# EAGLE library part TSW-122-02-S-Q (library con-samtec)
THROUGH-HOLE .025" SQ POST HEADER Source: Samtec TSW.pdf
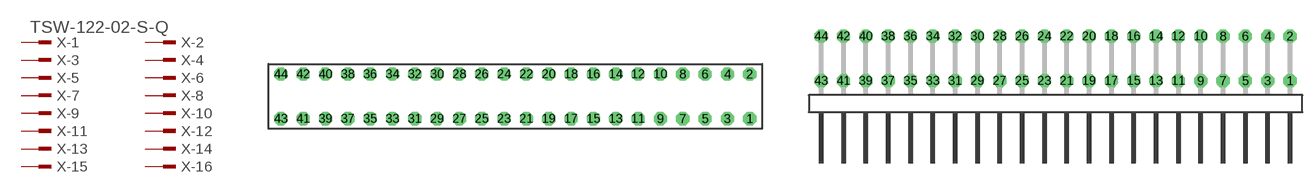
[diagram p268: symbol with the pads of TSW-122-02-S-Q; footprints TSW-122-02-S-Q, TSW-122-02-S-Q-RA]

Designator prefix X; gates -1=MPINV -2=MPIN -3=MPIN -4=MPIN -5=MPIN -6=MPIN -7=MPIN -8=MPIN -9=MPIN -10=MPIN -11=MPIN -12=MPIN -13=MPIN -14=MPIN -15=MPIN -16=MPIN -17=MPIN -18=MPIN -19=MPIN -20=MPIN -21=MPIN -22=MPIN -23=MPIN -24=MPIN -25=MPIN -26=MPIN -27=MPIN -28=MPIN -29=MPIN -30=MPIN -31=MPIN -32=MPIN -33=MPIN -34=MPIN -35=MPIN -36=MPIN -37=MPIN -38=MPIN -39=MPIN -40=MPIN -41=MPIN -42=MPIN -43=MPIN -44=MPIN

## TSW-122-02-S-Q (OC_FARNELL: unknown; OC_NEWARK: unknown)  [TSW-122-02-S-Q]
1  -1:1  pas
2  -2:1  pas
3  -3:1  pas
4  -4:1  pas
5  -5:1  pas
6  -6:1  pas
7  -7:1  pas
8  -8:1  pas
9  -9:1  pas
10  -10:1  pas
11  -11:1  pas
12  -12:1  pas
13  -13:1  pas
14  -14:1  pas
15  -15:1  pas
16  -16:1  pas
17  -17:1  pas
18  -18:1  pas
19  -19:1  pas
20  -20:1  pas
21  -21:1  pas
22  -22:1  pas
23  -23:1  pas
24  -24:1  pas
25  -25:1  pas
26  -26:1  pas
27  -27:1  pas
28  -28:1  pas
29  -29:1  pas
30  -30:1  pas
31  -31:1  pas
32  -32:1  pas
33  -33:1  pas
34  -34:1  pas
35  -35:1  pas
36  -36:1  pas
37  -37:1  pas
38  -38:1  pas
39  -39:1  pas
40  -40:1  pas
41  -41:1  pas
42  -42:1  pas
43  -43:1  pas
44  -44:1  pas

## TSW-122-02-S-Q-RA (OC_FARNELL: unknown; OC_NEWARK: unknown)  [TSW-122-02-S-Q-RA]
Pads as for TSW-122-02-S-Q

## Footprint TSW-122-02-S-Q (pad centres in mm)
THROUGH-HOLE .025" SQ POST HEADER Source: Samtec TSW.pdf
drill 1 pad 1.5 octagon: 1 26.67,-2.54; 2 26.67,2.54; 3 24.13,-2.54; 4 24.13,2.54; 5 21.59,-2.54; 6 21.59,2.54; 7 19.05,-2.54; 8 19.05,2.54; 9 16.51,-2.54; 10 16.51,2.54; 11 13.97,-2.54; 12 13.97,2.54; 13 11.43,-2.54; 14 11.43,2.54; 15 8.89,-2.54; 16 8.89,2.54; 17 6.35,-2.54; 18 6.35,2.54; 19 3.81,-2.54; 20 3.81,2.54; 21 1.27,-2.54; 22 1.27,2.54; 23 -1.27,-2.54; 24 -1.27,2.54; 25 -3.81,-2.54; 26 -3.81,2.54; 27 -6.35,-2.54; 28 -6.35,2.54; 29 -8.89,-2.54; 30 -8.89,2.54; 31 -11.43,-2.54; 32 -11.43,2.54; 33 -13.97,-2.54; 34 -13.97,2.54; 35 -16.51,-2.54; 36 -16.51,2.54; 37 -19.05,-2.54; 38 -19.05,2.54; 39 -21.59,-2.54; 40 -21.59,2.54; 41 -24.13,-2.54; 42 -24.13,2.54; 43 -26.67,-2.54; 44 -26.67,2.54

## Footprint TSW-122-02-S-Q-RA (pad centres in mm)
THROUGH-HOLE .025" SQ POST HEADER Source: Samtec TSW.pdf
drill 1 pad 1.5 octagon: 1 26.67,1.524; 2 26.67,6.604; 3 24.13,1.524; 4 24.13,6.604; 5 21.59,1.524; 6 21.59,6.604; 7 19.05,1.524; 8 19.05,6.604; 9 16.51,1.524; 10 16.51,6.604; 11 13.97,1.524; 12 13.97,6.604; 13 11.43,1.524; 14 11.43,6.604; 15 8.89,1.524; 16 8.89,6.604; 17 6.35,1.524; 18 6.35,6.604; 19 3.81,1.524; 20 3.81,6.604; 21 1.27,1.524; 22 1.27,6.604; 23 -1.27,1.524; 24 -1.27,6.604; 25 -3.81,1.524; 26 -3.81,6.604; 27 -6.35,1.524; 28 -6.35,6.604; 29 -8.89,1.524; 30 -8.89,6.604; 31 -11.43,1.524; 32 -11.43,6.604; 33 -13.97,1.524; 34 -13.97,6.604; 35 -16.51,1.524; 36 -16.51,6.604; 37 -19.05,1.524; 38 -19.05,6.604; 39 -21.59,1.524; 40 -21.59,6.604; 41 -24.13,1.524; 42 -24.13,6.604; 43 -26.67,1.524; 44 -26.67,6.604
